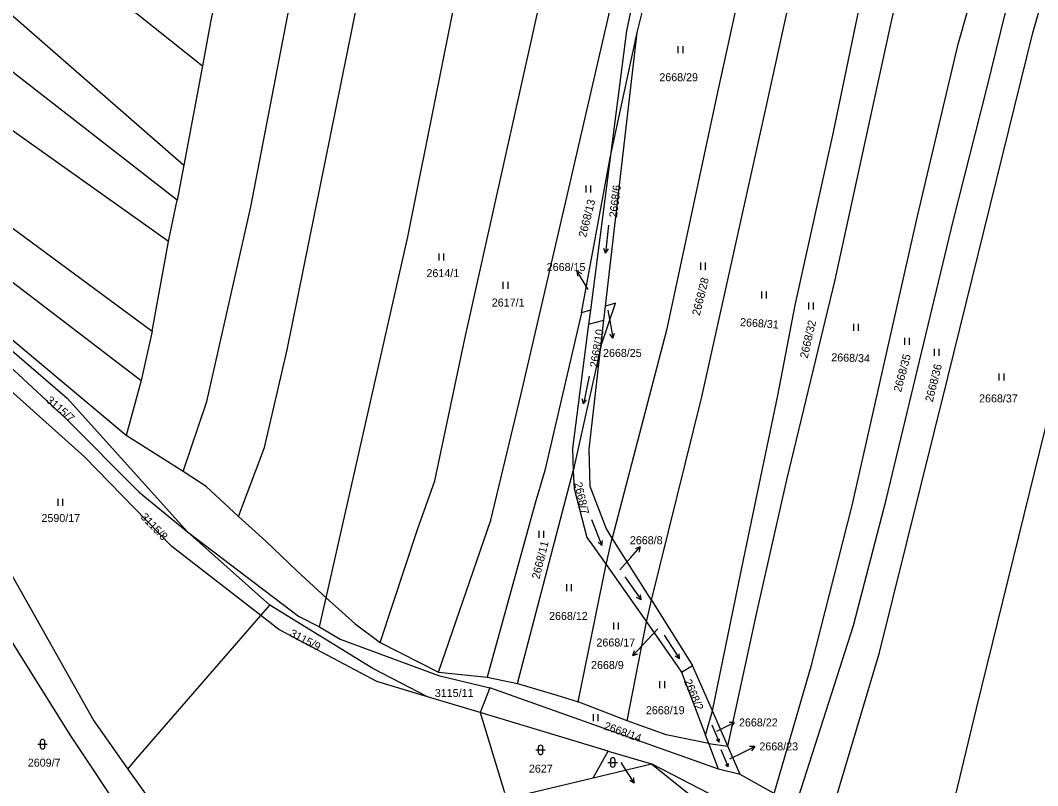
# Model space of a CAD drawing. Extents: x -755528 to -748832, y -1118122 to -1111095.
# Drawn here: x -753923.8 to -753707.7, y -1115348.1 to -1115185.5 of the extents above; entities that cross this region are included whole.
import ezdxf

# ---------------------------------------------------------------- set-up
doc = ezdxf.new("R2010")
doc.units = 0
for name, color, linetype in [('DZ_DO_PUPFL', 7, 'Continuous'), ('DZ_NAD_ZPF', 7, 'Continuous'), ('legenda barvy', 7, 'Continuous'), ('TZ_UMVŽST', 7, 'Continuous')]:
    doc.layers.add(name, color=color, linetype=linetype)

msp = doc.modelspace()

# ---------------------------------------------------------------- linework, layer by layer
at = {"layer": 'DZ_NAD_ZPF'}
for p, q in [((-753792.82, -1115188.05), (-753791.53, -1115182.96)), ((-753799.53, -1115246.2), (-753792.82, -1115188.05)), ((-753798.54, -1115214.71), (-753792.82, -1115188.05)), ((-753885.13, -1115195.17), (-753889.08, -1115216.26)), ((-753804.65, -1115247.63), (-753798.54, -1115214.71)), ((-753798.54, -1115214.71), (-753802.74, -1115247.1)), ((-753889.08, -1115216.26), (-753890.53, -1115223.67)), ((-753892.38, -1115232.5), (-753890.53, -1115223.67)), ((-753895.87, -1115251.53), (-753892.38, -1115232.5)), ((-753799.87, -1115249.18), (-753799.53, -1115246.2)), ((-753802.74, -1115247.1), (-753804.65, -1115247.63)), ((-753802.74, -1115247.1), (-753803.12, -1115250.02)), ((-753803.12, -1115250.02), (-753799.87, -1115249.18)), ((-753800.52, -1115254.8), (-753799.87, -1115249.18)), ((-753895.87, -1115251.53), (-753898.17, -1115262.01)), ((-753800.52, -1115254.8), (-753806.37, -1115281.21)), ((-753898.17, -1115262.01), (-753901.37, -1115273.67)), ((-753889.22, -1115281.32), (-753901.37, -1115273.67)), ((-753818.24, -1115326.4), (-753806.37, -1115281.21)), ((-753870.81, -1115309.77), (-753888.32, -1115294.15)), ((-753799.42, -1115301.11), (-753798.09, -1115295.51)), ((-753789.77, -1115308.69), (-753798.09, -1115295.51)), ((-753805.37, -1115330.32), (-753799.42, -1115301.11)), ((-753799.42, -1115301.11), (-753790.84, -1115313.32)), ((-753860.3, -1115314.35), (-753858.9, -1115308.17)), ((-753790.84, -1115313.32), (-753789.77, -1115308.69)), ((-753872.72, -1115311.97), (-753870.81, -1115309.77)), ((-753794.95, -1115334.31), (-753790.84, -1115313.32)), ((-753847.38, -1115317.7), (-753835, -1115324.01)), ((-753835, -1115324.01), (-753824.69, -1115325.05)), ((-753783.35, -1115323.99), (-753781.01, -1115322.59)), ((-753783.35, -1115323.99), (-753778.27, -1115337.37)), ((-753776.81, -1115332.22), (-753781.01, -1115322.59)), ((-753824.69, -1115325.05), (-753818.24, -1115326.4)), ((-753824.08, -1115327.29), (-753826.14, -1115332.58)), ((-753775.54, -1115344.57), (-753824.08, -1115327.29)), ((-753826.14, -1115332.58), (-753837.33, -1115329.22)), ((-753794.95, -1115334.31), (-753805.37, -1115330.32)), ((-753826.14, -1115332.58), (-753820.98, -1115349.55)), ((-753798.93, -1115340.75), (-753826.14, -1115332.58)), ((-753778.27, -1115337.37), (-753776.81, -1115332.22)), ((-753773.54, -1115339.7), (-753776.81, -1115332.22)), ((-753777.59, -1115339.15), (-753778.27, -1115337.37)), ((-753775.54, -1115344.57), (-753777.59, -1115339.15)), ((-753777.59, -1115339.15), (-753773.54, -1115339.7)), ((-753802.15, -1115346.45), (-753798.93, -1115340.75)), ((-753798.93, -1115340.75), (-753789.77, -1115343.5)), ((-753770.91, -1115345.72), (-753773.54, -1115339.7)), ((-753802.15, -1115346.45), (-753789.77, -1115343.5)), ((-753789.77, -1115343.5), (-753771.64, -1115357.97)), ((-753769.28, -1115354), (-753789.77, -1115343.5)), ((-753770.91, -1115345.72), (-753775.54, -1115344.57)), ((-753763.66, -1115349.76), (-753770.91, -1115345.72)), ((-753820.58, -1115350.85), (-753802.15, -1115346.45))]:
    msp.add_line(p, q, dxfattribs=at)
for points in [[(-754092.56, -1115001.86), (-754083.78, -1115010.11), (-754036.35, -1115058.43), (-754002.53, -1115092.73), (-753974.88, -1115120.81), (-753951.98, -1115141.28), (-753920.2, -1115167.2), (-753885.13, -1115195.17)], [(-754099.23, -1115017.16), (-754071.99, -1115042.5), (-754040.56, -1115075.94), (-753987.64, -1115131.05), (-753956.21, -1115159.07), (-753927.01, -1115183.18), (-753889.08, -1115216.26)], [(-753890.53, -1115223.67), (-753927.3, -1115195.1), (-753947.38, -1115178.68), (-753985.64, -1115144.56), (-754044.93, -1115080.73), (-754102.41, -1115025.12)], [(-753892.38, -1115232.5), (-753935.02, -1115202.25), (-753964.88, -1115176.92), (-754000.67, -1115141.28), (-754049.9, -1115085.22), (-754105.8, -1115035.43)], [(-754104.19, -1115052.69), (-754057.32, -1115097.07), (-754020.94, -1115141.1), (-754004.91, -1115159.19), (-753984.34, -1115182.87), (-753947.29, -1115213.59), (-753895.87, -1115251.53)], [(-753889.22, -1115281.32), (-753884.22, -1115266.45), (-753874.89, -1115225.11), (-753861.01, -1115153.01), (-753848.53, -1115088.3), (-753842.2, -1115068.25), (-753836.55, -1115053.32)], [(-754097.68, -1115063.04), (-754067.54, -1115099.8), (-754038.56, -1115135.33), (-754025.69, -1115151.2), (-754006.38, -1115173.92), (-753993.42, -1115187.68), (-753935.03, -1115233.93), (-753898.17, -1115262.01)], [(-753877.5, -1115290.9), (-753872.01, -1115276.25), (-753867.16, -1115255.51), (-753849.81, -1115169.74), (-753839.59, -1115116.86), (-753832.48, -1115088.95), (-753825.23, -1115068.3)], [(-753858.9, -1115308.17), (-753841.51, -1115231.47), (-753822.03, -1115134.25), (-753813.93, -1115100.17), (-753807.76, -1115085.35)], [(-753847.38, -1115317.7), (-753839.5, -1115293.67), (-753835.79, -1115283.35), (-753829.38, -1115253.16), (-753813.14, -1115180.08), (-753811.71, -1115171.33), (-753803.55, -1115133.82), (-753797.64, -1115108.22), (-753794.18, -1115095.22)], [(-753835, -1115324.01), (-753823.86, -1115291.7), (-753817.46, -1115264.86), (-753807.73, -1115223.09), (-753797.54, -1115178.81), (-753788.44, -1115138.67), (-753780.79, -1115105.85)], [(-753775.87, -1115116), (-753778.95, -1115118.54), (-753785.28, -1115127.14), (-753793.95, -1115182.36), (-753795.04, -1115187.69), (-753798.54, -1115214.71)], [(-753758.02, -1115122.91), (-753767.5, -1115163.21), (-753775.58, -1115200.14), (-753786.55, -1115251.31), (-753798.09, -1115295.51)], [(-753901.37, -1115273.67), (-753946.58, -1115235.91), (-753989.78, -1115207.19), (-754013.22, -1115183.85), (-754053.94, -1115130.27)], [(-753789.77, -1115308.69), (-753779.04, -1115265.51), (-753765.42, -1115203.94), (-753755.29, -1115157.75), (-753748.44, -1115130.08)], [(-753776.81, -1115332.22), (-753770.23, -1115300.11), (-753762.92, -1115265.2), (-753759.22, -1115246.04), (-753751.08, -1115209.25), (-753741.66, -1115163.79), (-753736.23, -1115139.2)], [(-753773.54, -1115339.7), (-753767.38, -1115311.34), (-753760.97, -1115283.14), (-753750.71, -1115240.6), (-753738.95, -1115186.68), (-753729.32, -1115144.37)], [(-753763.66, -1115349.76), (-753755.73, -1115322.54), (-753747.14, -1115288.61), (-753733.22, -1115227.13), (-753724.6, -1115190.55), (-753714.65, -1115155.34)], [(-753759.06, -1115352.33), (-753746.83, -1115314.09), (-753739.87, -1115287.41), (-753725.63, -1115228.17), (-753718.54, -1115199.99), (-753708.66, -1115159.82)], [(-753752.14, -1115356.18), (-753741.33, -1115319.81), (-753726.82, -1115261.41), (-753708.77, -1115188.16), (-753702.08, -1115164.74)], [(-753881.66, -1115177.17), (-753883.46, -1115185.86), (-753885.13, -1115195.17)], [(-753729.17, -1115366.77), (-753720.7, -1115331.7), (-753704.97, -1115267.86), (-753693.75, -1115221.04), (-753683.72, -1115178.46)], [(-753943.95, -1115243.78), (-753926.66, -1115254.82), (-753913.89, -1115265.76), (-753888.32, -1115294.15)], [(-753800.52, -1115254.8), (-753797.43, -1115245.62), (-753799.53, -1115246.2)], [(-753804.65, -1115247.63), (-753812.44, -1115281.13), (-753814.5, -1115288.09), (-753824.69, -1115325.05)], [(-753803.12, -1115250.02), (-753806.56, -1115276.46), (-753806.37, -1115281.21)], [(-753931.23, -1115254.31), (-753914.3, -1115269.92), (-753898.62, -1115285.75), (-753888.32, -1115294.15)], [(-753798.09, -1115295.51), (-753799.42, -1115293.4), (-753800.83, -1115289.7), (-753802.78, -1115284.55), (-753803.03, -1115276.6), (-753800.52, -1115254.8)], [(-753872.72, -1115311.97), (-753891.67, -1115297.26), (-753910.25, -1115278.23), (-753932.17, -1115258.63), (-753934.24, -1115257.26)], [(-753949.02, -1115271.88), (-753947.7, -1115272.48), (-753927.24, -1115300.6), (-753908.24, -1115334.31), (-753900.99, -1115344.57)], [(-753877.5, -1115290.9), (-753884.34, -1115284.53), (-753889.22, -1115281.32)], [(-753806.37, -1115281.21), (-753806.22, -1115284.94), (-753803.46, -1115295.37), (-753802.53, -1115296.69), (-753799.42, -1115301.11)], [(-753888, -1115393.39), (-753897.23, -1115385.64), (-753900.87, -1115355.95), (-753913.23, -1115337.3), (-753925.17, -1115318.28), (-753934.99, -1115302.4), (-753948.16, -1115284.48)], [(-753858.9, -1115308.17), (-753865.11, -1115302.44), (-753871.71, -1115296.18), (-753877.5, -1115290.9)], [(-753888.32, -1115294.15), (-753864.75, -1115312.08), (-753860.3, -1115314.35)], [(-753858.9, -1115308.17), (-753852.68, -1115313.74), (-753847.38, -1115317.7)], [(-753789.77, -1115308.69), (-753783.3, -1115318.96), (-753781.01, -1115322.59)], [(-753837.33, -1115329.22), (-753848.98, -1115323.18), (-753870.81, -1115309.77)], [(-753900.99, -1115344.57), (-753899.3, -1115342.55), (-753872.72, -1115311.97)], [(-753837.33, -1115329.22), (-753848.11, -1115325.98), (-753868.94, -1115314.9), (-753872.72, -1115311.97)], [(-753860.3, -1115314.35), (-753855.88, -1115316.98), (-753835.01, -1115324.72), (-753824.08, -1115327.29)], [(-753790.84, -1115313.32), (-753784.13, -1115322.87), (-753783.35, -1115323.99)], [(-753818.24, -1115326.4), (-753809.9, -1115328.86), (-753805.37, -1115330.32)], [(-753777.59, -1115339.15), (-753786.63, -1115337.29), (-753794.95, -1115334.31)], [(-753900.99, -1115344.57), (-753894.5, -1115353.77), (-753893.68, -1115357.94), (-753889.87, -1115377.8), (-753878.61, -1115383.77), (-753858.42, -1115388.67)]]:
    msp.add_lwpolyline(points, dxfattribs=at)
at = {"layer": 'legenda barvy'}
for p, q in [((-753804.04, -1115241.29), (-753805.586, -1115238.718)), ((-753805.586, -1115238.718), (-753804.641, -1115239.318)), ((-753805.586, -1115238.718), (-753805.499, -1115239.834)), ((-753803.19, -1115242.69), (-753804.04, -1115241.29)), ((-753799, -1115247.04), (-753798.47, -1115250.09)), ((-753798.47, -1115250.09), (-753797.949, -1115253.045)), ((-753797.949, -1115253.045), (-753798.616, -1115252.146)), ((-753797.949, -1115253.045), (-753797.63, -1115251.972)), ((-753794.16, -1115299.62), (-753792.152, -1115297.39)), ((-753792.152, -1115297.39), (-753793.194, -1115297.799)), ((-753792.152, -1115297.39), (-753792.45, -1115298.469)), ((-753796.49, -1115302.25), (-753794.16, -1115299.62)), ((-753788.42, -1115314.82), (-753791.66, -1115318.29)), ((-753791.66, -1115318.29), (-753793.707, -1115320.485)), ((-753793.707, -1115320.485), (-753793.39, -1115319.411)), ((-753793.707, -1115320.485), (-753792.657, -1115320.094)), ((-753774.86, -1115336), (-753772.163, -1115334.684)), ((-753772.163, -1115334.684), (-753773.282, -1115334.673)), ((-753772.163, -1115334.684), (-753772.843, -1115335.574)), ((-753775.91, -1115336.52), (-753774.86, -1115336)), ((-753773.13, -1115342.38), (-753770.52, -1115341.1)), ((-753770.52, -1115341.1), (-753767.823, -1115339.784)), ((-753767.823, -1115339.784), (-753768.942, -1115339.773)), ((-753767.823, -1115339.784), (-753768.503, -1115340.674)), ((-753796.29, -1115343.19), (-753795.05, -1115345.07)), ((-753795.05, -1115345.07), (-753793.416, -1115347.587)), ((-753793.416, -1115347.587), (-753794.381, -1115347.02)), ((-753793.416, -1115347.587), (-753793.541, -1115346.474))]:
    msp.add_line(p, q, dxfattribs=at)
at = {"layer": 'TZ_UMVŽST'}
for p, q in [((-753784.061, -1115192.49), (-753784.061, -1115190.99)), ((-753783.06, -1115192.49), (-753783.06, -1115190.99)), ((-753803.611, -1115222.1), (-753803.611, -1115220.6)), ((-753802.61, -1115222.1), (-753802.61, -1115220.6)), ((-753798.877, -1115229.013), (-753799.504, -1115234.98)), ((-753834.881, -1115236.51), (-753834.881, -1115235.01)), ((-753833.88, -1115236.51), (-753833.88, -1115235.01)), ((-753799.504, -1115234.98), (-753799.9, -1115233.956)), ((-753799.504, -1115234.98), (-753798.903, -1115234.06)), ((-753779.301, -1115238.48), (-753779.301, -1115236.98)), ((-753778.3, -1115238.48), (-753778.3, -1115236.98)), ((-753821.241, -1115242.56), (-753821.241, -1115241.06)), ((-753820.24, -1115242.56), (-753820.24, -1115241.06)), ((-753766.341, -1115244.59), (-753766.341, -1115243.09)), ((-753765.34, -1115244.59), (-753765.34, -1115243.09)), ((-753756.331, -1115246.92), (-753756.331, -1115245.42)), ((-753755.33, -1115246.92), (-753755.33, -1115245.42)), ((-753746.771, -1115251.45), (-753746.771, -1115249.95)), ((-753745.77, -1115251.45), (-753745.77, -1115249.95)), ((-753735.931, -1115254.46), (-753735.931, -1115252.96)), ((-753734.93, -1115254.46), (-753734.93, -1115252.96)), ((-753729.641, -1115256.77), (-753729.641, -1115255.27)), ((-753728.64, -1115256.77), (-753728.64, -1115255.27)), ((-753802.978, -1115261.101), (-753804.226, -1115266.969)), ((-753715.861, -1115262.02), (-753715.861, -1115260.52)), ((-753714.86, -1115262.02), (-753714.86, -1115260.52)), ((-753804.226, -1115266.969), (-753804.513, -1115265.909)), ((-753804.226, -1115266.969), (-753803.532, -1115266.118)), ((-753915.811, -1115288.65), (-753915.811, -1115287.15)), ((-753914.81, -1115288.65), (-753914.81, -1115287.15)), ((-753802.535, -1115291.548), (-753800.288, -1115297.111)), ((-753813.631, -1115295.46), (-753813.631, -1115293.96)), ((-753812.63, -1115295.46), (-753812.63, -1115293.96)), ((-753800.288, -1115297.111), (-753800.189, -1115296.017)), ((-753800.288, -1115297.111), (-753801.119, -1115296.392)), ((-753795.398, -1115303.702), (-753791.956, -1115308.616)), ((-753807.761, -1115306.77), (-753807.761, -1115305.27)), ((-753806.76, -1115306.77), (-753806.76, -1115305.27)), ((-753791.956, -1115308.616), (-753792.928, -1115308.104)), ((-753791.956, -1115308.616), (-753792.106, -1115307.528)), ((-753797.761, -1115314.94), (-753797.761, -1115313.44)), ((-753796.76, -1115314.94), (-753796.76, -1115313.44)), ((-753787.052, -1115316.123), (-753783.784, -1115321.155)), ((-753783.784, -1115321.155), (-753784.737, -1115320.609)), ((-753783.784, -1115321.155), (-753783.896, -1115320.062)), ((-753787.951, -1115327.39), (-753787.951, -1115325.89)), ((-753786.95, -1115327.39), (-753786.95, -1115325.89)), ((-753802.091, -1115334.4), (-753802.091, -1115332.9)), ((-753801.09, -1115334.4), (-753801.09, -1115332.9)), ((-753776.956, -1115335.163), (-753775.385, -1115338.863)), ((-753919.631, -1115338.791), (-753919.631, -1115339.792)), ((-753918.629, -1115339.792), (-753918.629, -1115338.791)), ((-753775.385, -1115338.863), (-753775.95, -1115338.392)), ((-753775.385, -1115338.863), (-753775.332, -1115338.129)), ((-753920.131, -1115339.291), (-753918.129, -1115339.291)), ((-753814.321, -1115340.501), (-753812.319, -1115340.501)), ((-753813.821, -1115340.001), (-753813.821, -1115341.002)), ((-753812.819, -1115341.002), (-753812.819, -1115340.001)), ((-753775.016, -1115340.423), (-753773.445, -1115344.123)), ((-753799.001, -1115343.181), (-753796.999, -1115343.181)), ((-753798.501, -1115342.681), (-753798.501, -1115343.682)), ((-753797.499, -1115343.682), (-753797.499, -1115342.681)), ((-753773.445, -1115344.123), (-753773.392, -1115343.389)), ((-753773.445, -1115344.123), (-753774.01, -1115343.652))]:
    msp.add_line(p, q, dxfattribs=at)
for centre, start, end in [((-753919.13, -1115338.7909), 0, 180), ((-753919.13, -1115339.7909), 180, 359.987886), ((-753813.32, -1115340.0009), 0, 180), ((-753813.32, -1115341.0009), 180, 359.987886), ((-753798, -1115342.6809), 0, 180), ((-753798, -1115343.6809), 180, 359.987886)]:
    msp.add_arc(centre, 0.5, start, end, dxfattribs=at)

# ---------------------------------------------------------------- texts
at = {"layer": 'DZ_DO_PUPFL'}
for s, p in [('2668/29', (-753788.09, -1115198.43)), ('2668/15', (-753812.013, -1115238.76)), ('2614/1', (-753837.56, -1115240.06)), ('2617/1', (-753823.69, -1115246.3)), ('2668/25', (-753800.06, -1115257.008)), ('2668/37', (-753720.16, -1115266.67)), ('2590/17', (-753919.36, -1115292.09)), ('2668/8', (-753794.35, -1115296.81)), ('2668/12', (-753811.52, -1115312.9)), ('2668/17', (-753801.45, -1115318.54)), ('2668/9', (-753802.605, -1115323.328)), ('3115/11', (-753835.79, -1115329.27)), ('2668/19', (-753790.94, -1115332.93)), ('2668/22', (-753771.17, -1115335.53)), ('2668/23', (-753766.83, -1115340.62)), ('2609/7', (-753922.26, -1115344.07)), ('2627', (-753815.8, -1115345.34))]:
    msp.add_text(s, height=1.7, dxfattribs=at).set_placement(p)
for s, rotation, p in [('2668/6', 83, (-753797.086, -1115227.473)), ('2668/13', 76, (-753803.665, -1115231.745)), ('2668/28', 76, (-753779.525, -1115248.355)), ('2668/31', 356, (-753770.979, -1115250.427)), ('2668/32', 77, (-753756.601, -1115257.431)), ('2668/10', 81, (-753801.18, -1115259.372)), ('2668/34', 358, (-753751.589, -1115257.909)), ('2668/35', 75, (-753736.748, -1115264.599)), ('2668/36', 76, (-753730.015, -1115266.715)), ('3115/7', 319, (-753918.487, -1115266.441)), ('2668/7', 283, (-753806.198, -1115283.831)), ('3115/8', 313.999997, (-753898.421, -1115291.15)), ('2668/11', 76, (-753813.585, -1115304.335)), ('3115/9', 332, (-753866.779, -1115316.24)), ('2668/2', 293, (-753782.912, -1115325.902)), ('2668/14', 340, (-753800.01, -1115336.078))]:
    msp.add_text(s, height=1.7, rotation=rotation, dxfattribs=at).set_placement(p)

doc.saveas('drawing.dxf')
